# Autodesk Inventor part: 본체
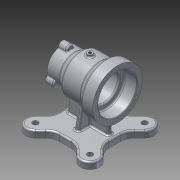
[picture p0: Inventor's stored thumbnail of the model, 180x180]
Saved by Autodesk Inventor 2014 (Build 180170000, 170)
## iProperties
Created: 2017-03
Part Number: 본체
Material: 알루미늄 6061
Document SubType Name: Modeling
Designer: user
Density: 2.71 g/cm^3
Appearance: 알루미늄 - 평지
Mass: 1014.89 g
Surface Area: 847.373 cm^2
Volume: 374.498 cm^3
Author: user
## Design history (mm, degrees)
sketch "스케치2"
  geometry: L1 (-45, 45)-(45, 45); L2 (45, 45)-(45, -45); L3 (45, -45)-(-45, -45); L4 (-45, -45)-(-45, 45); L5 (-49.497, 49.497)-(45, -45); L6 (45, 45)-(-45, -45); L7 (-37.477, 61.518)-(-20.958, 45); L8 (-61.518, 37.477)-(-45, 20.958); L9 (-45, 45)-(49.497, -49.497); L10 (49.497, 49.497)-(-49.497, -49.497); L11 (-61.518, -37.477)-(-45, -20.958); L12 (-37.477, -61.518)-(-20.958, -45); L13 (37.477, -61.518)-(20.958, -45); L14 (37.477, 61.518)-(20.958, 45); L15 (61.518, -37.477)-(45, -20.958); L16 (61.518, 37.477)-(45, 20.958); A1 r 70 centre (0, 0) between (-49.497, 49.497) and (49.497, 49.497); A2 r 17 centre (-49.497, 49.497) between (-37.477, 61.518) and (-61.518, 37.477); A3 r 17 centre (49.497, 49.497) between (37.477, 37.477) and (33.103, 45); A4 r 17 centre (49.497, -49.497) between (37.477, -61.518) and (61.518, -37.477); A5 r 17 centre (-49.497, -49.497) between (-61.518, -37.477) and (-37.477, -61.518); 1 further point
  constraints: 32 end point, 14 point on circle, 14 point on line, 8 tangent, 7 parallel, 5 centre point, 4 perpendicular, 3 coincident, 1 collinear, 1 horizontal, 1 midpoint
  dimensions: "d19" = 90 distance of L2.end L3.end; "d20" = 90 distance of L1.end L2.end; "d21" = 140 diameter of A1; "d24" = 34 diameter of A2; "d29" = 34 diameter of A3; "d30" = 34 diameter of A4; "d32" = 34 diameter of A5
extrude "돌출2" new body sketch "스케치2" distance "d22" = 12; taper "d23" = 0 deg
extrude "돌출3" join sketch "스케치2" distance "d25" = 12; taper "d26" = 0 deg
extrude "돌출4" join sketch "스케치2" distance "d27" = 12; taper "d28" = 0 deg
extrude "돌출5" cut sketch "스케치2" distance "d41" = 12; taper "d42" = 0 deg
extrude "돌출6" join sketch "스케치2" distance "d43" = 12; taper "d44" = 0 deg
fillet "모깎기1" dims "d45" = 25
fillet "모깎기2" dims "d46" = 25
sketch "스케치3"
  geometry: C1 r 5 at (-49.497, 49.497); C2 r 5 at (49.497, 49.497); C3 r 5 at (49.497, -49.497); C4 r 5 at (-49.497, -49.497); A1 r 17 centre (49.497, -49.497) between (37.477, -61.518) and (61.518, -37.477) reference; A2 r 17 centre (49.497, 49.497) between (61.518, 37.477) and (37.477, 61.518) reference; A3 r 17 centre (-49.497, 49.497) between (-37.477, 61.518) and (-61.518, 37.477) reference; A4 r 17 centre (-49.497, -49.497) between (-61.518, -37.477) and (-37.477, -61.518) reference; 1 further point
  constraints: 4 centre point, 4 coincident
  dimensions: "d47" = 10 diameter of C1; "d48" = 10 diameter of C2; "d49" = 10 diameter of C3; "d50" = 10 diameter of C4
extrude "돌출7" cut sketch "스케치3" distance "d51" = 12; taper "d52" = 0 deg
sketch "스케치4"
  geometry: L1 (-50, 82)-(50, 82); L2 (10.603, 0)-(-10.603, 0) reference; L3 (-50, 82)-(-50, 127); L4 (-50, 127)-(-30, 127); L5 (-30, 127)-(-19, 118); L6 (-19, 118)-(15, 118); L7 (15, 118)-(27, 109.5); L8 (27, 109.5)-(50, 109.5); L9 (50, 109.5)-(50, 82); 3 further points
  constraints: 16 end point, 3 perpendicular, 2 midpoint, 2 parallel, 1 horizontal, 1 vertical alignment
  dimensions: "d53" = 82 distance between parallel lines of L1 L2; "d54" = 90 diameter of L4 L1; "d55" = 20 distance of L3.end L4.end; "d56" = 72 diameter of L6 L1; "d57" = 55 diameter of L8 L1; "d58" = 31 distance from line of L5.end L3; "d59" = 65 distance from line of L6.end L3; "d60" = 100 distance between parallel lines of L9 L3; "d61" = 23 distance from line of L7.end L9
revolve "회전1" sketch "스케치4" stored, may be unused: angle "d62" = 90 deg
node "작업 평면1"
sketch "스케치7"
  geometry: L1 (50, 45)-(50, -45) reference; C1 r 5 at (0, 0); 2 further points
  constraints: 1 centre point, 1 horizontal alignment, 1 midpoint
  dimensions: "d75" = 10 diameter of C1; "d76" = 50 distance from line of C1.centre L1
extrude "돌출10" join sketch "스케치7" stored distance "d77" = 12; taper "d78" = 0 deg
sketch "스케치8"
  geometry: L1 (-50, 37)-(-50, 127) reference; L2 (-30, 37)-(-30, 127) reference; L3 (50, 54.5)-(50, 109.5) reference; L4 (-50, 82)-(50, 82); L5 (-27, 114)-(-27, 111); L6 (-24, 108)-(17, 108); L7 (20, 105)-(20, 102.5); L8 (23, 99.5)-(50, 99.5); L9 (-30, 117)-(-50, 117); A1 r 3 centre (-30, 114) between (-27, 114) and (-30, 117); A2 r 3 centre (-24, 111) between (-27, 111) and (-24, 108); A3 r 3 centre (17, 105) between (20, 105) and (17, 108); A4 r 3 centre (23, 102.5) between (20, 102.5) and (23, 99.5); 5 further points
  constraints: 12 end point, 10 point on line, 8 point on circle, 8 tangent, 4 centre point, 4 perpendicular, 3 equal radius, 2 midpoint, 1 parallel
  dimensions: "d80" = 70 diameter of L9 L4; "d81" = 23 distance of point (-27, 117) L9.end; "d82" = 52 diameter of L6 L4; "d83" = 47 distance of point (-27, 108) point (20, 108); "d84" = 35 diameter of L8 L4; "d85" = 30 distance of point (20, 99.5) L8.end (derived); "d86" = 3 radius of A1
revolve "회전2" sketch "스케치8" stored, may be unused: angle "d87" = 90 deg
sketch "스케치9" dims "d88" = 80
  geometry: C1 r 35 at (0, 0) reference; C2 r 45 at (0, 0) reference; 3 further points
  constraints: 2 horizontal alignment, 1 coincident, 2 other
hole "구멍1" sketch "스케치9" at (-40, 0) diameter "d89" = 3.242; stored, may be unused: countersink angle "d93" = 90 deg, drill point angle "d95" = 118 deg; dims "d90" = 9, "d91" = 4, "d92" = 2, "d94" = 11
fillet "모깎기3" dims "d99" = 3
fillet "모깎기4" dims "d100" = 3
chamfer "모따기1" distance "d101" = 1; stored, may be unused: second distance "d102" = 2, angle "d103" = 45 deg
sketch "스케치10"
  geometry: C1 r 7 at (27.5, 0); 2 further points
  constraints: 2 horizontal alignment, 1 centre point, 1 other
  dimensions: "d107" = 7 radius of C1
extrude "돌출11" join sketch "스케치10" distance "d108" = 15; taper "d109" = 0 deg
fillet "모깎기8" dims "d110" = 3
fillet "모깎기9" dims "d111" = 1
sketch "스케치11"
  geometry: A1 r 7 centre (0, 0) between (-0.127, -6.999) and (-0.127, 6.999) reference; 2 further points
  constraints: 1 coincident
hole "구멍2" sketch "스케치11" at (0, 0) diameter "d115" = 3.242; stored, may be unused: countersink angle "d119" = 90 deg, drill point angle "d121" = 118 deg; dims "d116" = 9, "d117" = 4, "d118" = 2, "d120" = 11
sketch "스케치12"
  geometry: C1 r 5 at (0, 0) reference; C2 r 2.5 at (0, 0)
  constraints: 1 centre point, 1 coincident
  dimensions: "d125" = 5 diameter of C2
extrude "돌출12" cut sketch "스케치12" stored distance "d126" = 15; taper "d127" = 0 deg
feature "스레드1" dims "d128" = 10, "d129" = 0
sketch "스케치13"
  geometry: L1 (-45, -10.603)-(-45, 10.603) reference; 2 further points
  constraints: 1 other
  dimensions: "d131" = 35 distance of point (0, 35) point (0, 0); "d132" = 45 distance from line of point (0, 35) L1
feature "엠보싱1" sketch "스케치13" dims "d19" = 90, "d20" = 90, "d21" = 140, "d24" = 34, "d29" = 34, "d30" = 34, "d32" = 34, "d133" = 0.5, "d134" = 0
fillet "모깎기11" dims "d137" = 3
sketch "스케치5"
  geometry: L1 (-37, 4)-(37, 4); L2 (37, 4)-(37, -4); L3 (37, -4)-(-37, -4); L4 (-37, -4)-(-37, 4); L5 (-37, 4)-(37, -4); L6 (37, 4)-(-37, -4); L7 (-0.958, -25)-(0.958, -25); L8 (28.281, -52.322)-(37.477, -61.518) reference; L9 (-37.477, -61.518)-(-28.281, -52.322) reference; 3 further points
  constraints: 14 end point, 4 point on line, 2 midpoint, 2 parallel, 1 horizontal, 1 perpendicular
  dimensions: "d63" = 74 distance of L2.end L3.end; "d64" = 8 distance of L1.end L2.end
extrude "돌출13" join sketch "스케치5" stored distance "d143" = 10; taper "d144" = 0 deg
sketch "스케치14"
  geometry: L1 (37, -4)-(-37, -4) reference; L2 (4, 25)-(-4, 25); L3 (-4, 25)-(-4, -4); L4 (4, -4)-(4, 25); L5 (4, 25)-(-4, -25); L6 (-4, 25)-(4, -25); 1 further point
  constraints: 10 end point, 2 midpoint, 2 point on line, 1 horizontal, 1 parallel, 1 perpendicular
  dimensions: "d146" = 50 distance of L5.end L2.end; "d147" = 8 distance between parallel lines of L4 L3; "d148" = 25 distance from line of point (0, 0) L2; "d149" = 29 distance of L2.end L3.end (derived)
extrude "돌출14" join sketch "스케치14" stored distance "d150" = 0; taper "d151" = 0 deg
feature "면 기울기4" dims angle "d152" = 10 deg
fillet "모깎기15" dims "d153" = 3
fillet "모깎기16" dims "d154" = 3
node "솔리드2"
pattern_circular "원형 패턴1" dims angle "d97" = 360 deg
pattern_circular "원형 패턴2" dims "d113" = 360 deg
pattern_circular "원형 패턴3" dims angle "d123" = 360 deg
mirror "대칭1"
node "투영된 루프2"
other parameters: "d74" = -122
